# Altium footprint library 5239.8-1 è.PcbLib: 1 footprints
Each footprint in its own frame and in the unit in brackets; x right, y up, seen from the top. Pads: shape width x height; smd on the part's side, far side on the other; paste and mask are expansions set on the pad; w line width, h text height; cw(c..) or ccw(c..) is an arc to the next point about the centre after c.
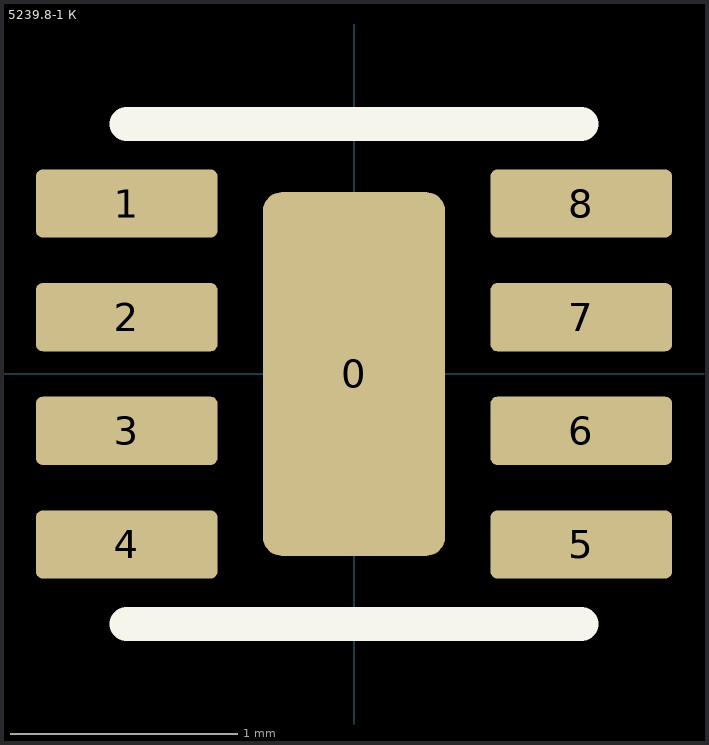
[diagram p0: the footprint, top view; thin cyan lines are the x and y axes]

## 5239.8-1 К [mm]
pads (9):
  rrect20% 0.8x1.6 smd mask+0: 0(0,0)
  rrect20% 0.8x0.3 smd mask+0: 1(-1,0.75) 2(-1,0.25) 3(-1,-0.25) 4(-1,-0.75) 5(1,-0.75) 6(1,-0.25) 7(1,0.25) 8(1,0.75)
Top Overlay:
  lines w0.15: -1,-1.1 1,-1.1 ; -1,1.1 1,1.1
  text "." at -2.1,0.8 h5
3D body "UDFN-8.step": height 0.6, standoff 0, extent -1,-1 1,1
